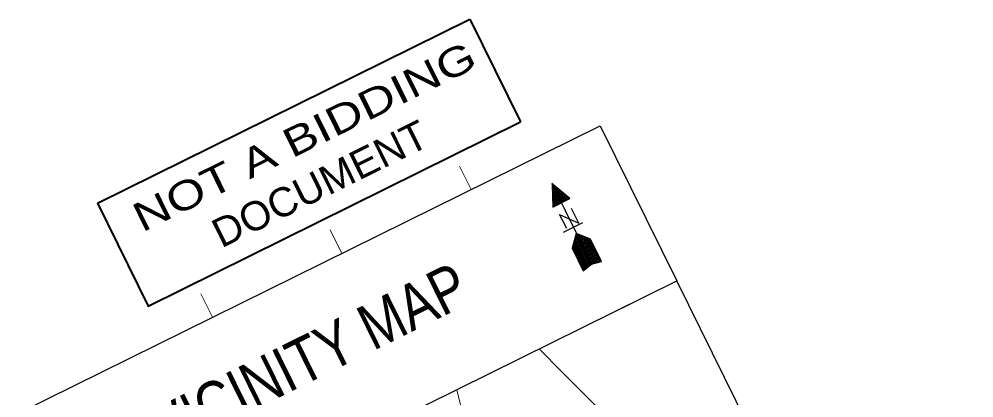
# Model space of a CAD drawing. Extents: x 2356606 to 2371222, y 6973096 to 6982644.
# Drawn here: x 2370560 to 2371222, y 6980646 to 6980908 of the extents above; entities that cross this region are included whole.
import ezdxf
from ezdxf.enums import TextEntityAlignment as Align

# ---------------------------------------------------------------- set-up
doc = ezdxf.new("R2010")
doc.units = 0
doc.header["$LTSCALE"] = 2
doc.layers.add('62', color=7, linetype='Continuous', lineweight=13)
doc.layers.add('63', color=7, linetype='Continuous', lineweight=13)

msp = doc.modelspace()

# ---------------------------------------------------------------- linework, layer by layer
at = {"layer": '62', "lineweight": 40}
for p, q in [((2370614.269, 6980780.584), (2370872.507, 6980908.033)), ((2370872.507, 6980908.033), (2370907.665, 6980836.794))]:
    msp.add_line(p, q, dxfattribs=at)
at = {"layer": '62'}
for p, q in [((2370865.446, 6980806.291), (2370873.467, 6980790.039)), ((2370929.594, 6980793.474), (2370930.018, 6980793.682)), ((2370935.697, 6980780.702), (2370929.603, 6980793.05)), ((2370929.611, 6980792.78), (2370930.539, 6980793.236)), ((2370929.616, 6980792.105), (2370931.07, 6980792.82)), ((2370935.134, 6980780.424), (2370929.635, 6980791.56)), ((2370929.644, 6980791.39), (2370931.602, 6980792.357)), ((2370929.649, 6980790.714), (2370932.111, 6980791.93)), ((2370929.685, 6980790.032), (2370932.633, 6980791.487)), ((2370929.712, 6980789.316), (2370933.162, 6980791.021)), ((2370929.72, 6980788.641), (2370933.673, 6980790.595)), ((2370936.262, 6980780.981), (2370929.968, 6980793.732)), ((2370936.825, 6980781.262), (2370931.171, 6980792.72)), ((2370937.372, 6980781.529), (2370932.353, 6980791.698)), ((2370937.956, 6980781.818), (2370933.564, 6980790.716)), ((2370934.565, 6980780.144), (2370929.685, 6980790.032)), ((2370934, 6980779.865), (2370929.718, 6980788.54)), ((2370929.734, 6980787.948), (2370934.216, 6980790.16)), ((2370929.752, 6980787.252), (2370934.737, 6980789.715)), ((2370933.435, 6980779.586), (2370929.761, 6980787.031)), ((2370929.769, 6980786.558), (2370935.277, 6980789.279)), ((2370929.805, 6980785.875), (2370935.798, 6980788.834)), ((2370932.87, 6980779.307), (2370929.813, 6980785.502)), ((2370929.822, 6980785.181), (2370936.339, 6980788.398)), ((2370929.839, 6980784.487), (2370936.86, 6980787.952)), ((2370932.305, 6980779.029), (2370929.845, 6980784.013)), ((2370929.872, 6980783.096), (2370937.902, 6980787.062)), ((2370929.873, 6980783.802), (2370937.381, 6980787.507)), ((2370929.889, 6980782.402), (2370938.423, 6980786.616)), ((2370929.925, 6980781.717), (2370938.964, 6980786.179)), ((2370929.94, 6980781.024), (2370939.485, 6980785.733)), ((2370929.949, 6980780.351), (2370939.997, 6980785.31)), ((2370929.993, 6980779.646), (2370940.548, 6980784.855)), ((2370930.011, 6980778.95), (2370941.069, 6980784.409)), ((2370930.018, 6980778.275), (2370941.58, 6980783.983)), ((2370938.521, 6980782.097), (2370934.767, 6980789.704)), ((2370939.065, 6980782.364), (2370935.939, 6980788.702)), ((2370939.651, 6980782.654), (2370937.162, 6980787.698)), ((2370940.196, 6980782.924), (2370938.344, 6980786.677)), ((2370940.761, 6980783.202), (2370939.536, 6980785.685)), ((2370941.346, 6980783.491), (2370940.758, 6980784.682)), ((2370931.742, 6980778.751), (2370929.897, 6980782.483)), ((2370931.175, 6980778.471), (2370929.932, 6980780.994)), ((2370930.61, 6980778.192), (2370929.985, 6980779.463)), ((2370930.065, 6980777.923), (2370930.035, 6980777.984)), ((2370775.769, 6980762.032), (2370783.79, 6980745.78)), ((2370944.683, 6980753.947), (2370951.849, 6980757.482)), ((2370944.921, 6980754.74), (2370951.074, 6980757.779)), ((2370945.145, 6980755.556), (2370950.291, 6980758.095)), ((2370945.381, 6980756.397), (2370949.518, 6980758.441)), ((2370945.618, 6980757.192), (2370948.745, 6980758.737)), ((2370955.648, 6980737.426), (2370945.707, 6980757.564)), ((2370945.842, 6980758.007), (2370947.983, 6980759.062)), ((2370956.157, 6980737.826), (2370945.968, 6980758.471)), ((2370946.07, 6980758.82), (2370947.199, 6980759.38)), ((2370956.65, 6980738.246), (2370946.223, 6980759.373)), ((2370957.225, 6980738.505), (2370946.847, 6980759.532)), ((2370957.85, 6980738.663), (2370947.732, 6980759.163)), ((2370958.455, 6980738.809), (2370948.595, 6980758.788)), ((2370959.111, 6980738.959), (2370949.489, 6980758.451)), ((2370959.725, 6980739.137), (2370950.372, 6980758.084)), ((2370960.339, 6980739.263), (2370951.226, 6980757.728)), ((2370943.513, 6980749.152), (2370956.287, 6980755.459)), ((2370943.537, 6980749.867), (2370955.723, 6980755.883)), ((2370943.751, 6980750.653), (2370954.948, 6980756.178)), ((2370943.791, 6980748.589), (2370956.566, 6980754.894)), ((2370952.173, 6980734.506), (2370943.915, 6980751.233)), ((2370943.987, 6980751.496), (2370954.177, 6980756.525)), ((2370944.07, 6980748.024), (2370956.843, 6980754.328)), ((2370952.667, 6980734.924), (2370944.169, 6980752.138)), ((2370944.212, 6980752.309), (2370953.394, 6980756.841)), ((2370944.35, 6980747.456), (2370957.122, 6980753.761)), ((2370953.162, 6980735.345), (2370944.428, 6980753.042)), ((2370944.468, 6980753.114), (2370952.622, 6980757.136)), ((2370944.628, 6980746.892), (2370957.402, 6980753.195)), ((2370953.668, 6980735.744), (2370944.683, 6980753.947)), ((2370944.908, 6980746.325), (2370957.682, 6980752.631)), ((2370954.163, 6980736.164), (2370944.94, 6980754.852)), ((2370945.187, 6980745.761), (2370957.959, 6980752.065)), ((2370954.658, 6980736.585), (2370945.196, 6980755.756)), ((2370955.155, 6980737.005), (2370945.452, 6980756.66)), ((2370945.465, 6980745.197), (2370958.239, 6980751.5)), ((2370945.742, 6980744.631), (2370958.517, 6980750.936)), ((2370960.981, 6980739.431), (2370952.129, 6980757.371)), ((2370961.588, 6980739.579), (2370952.993, 6980756.994)), ((2370962.212, 6980739.739), (2370953.877, 6980756.628)), ((2370962.857, 6980739.904), (2370954.78, 6980756.271)), ((2370963.462, 6980740.053), (2370955.634, 6980755.915)), ((2370951.182, 6980733.666), (2370943.402, 6980749.425)), ((2370951.696, 6980734.094), (2370943.678, 6980750.34)), ((2370946.021, 6980744.065), (2370958.794, 6980750.37)), ((2370946.303, 6980743.503), (2370959.075, 6980749.805)), ((2370946.572, 6980742.958), (2370959.344, 6980749.26)), ((2370946.859, 6980742.372), (2370959.634, 6980748.677)), ((2370947.138, 6980741.807), (2370959.911, 6980748.111)), ((2370947.409, 6980741.262), (2370960.181, 6980747.567)), ((2370947.696, 6980740.677), (2370960.469, 6980746.981)), ((2370947.964, 6980740.133), (2370960.739, 6980746.437)), ((2370948.244, 6980739.566), (2370961.016, 6980745.872)), ((2370948.532, 6980738.982), (2370961.305, 6980745.286)), ((2370948.801, 6980738.438), (2370961.574, 6980744.742)), ((2370949.08, 6980737.871), (2370961.853, 6980744.177)), ((2370949.36, 6980737.309), (2370962.132, 6980743.61)), ((2370949.637, 6980736.743), (2370962.412, 6980743.048)), ((2370949.917, 6980736.176), (2370962.689, 6980742.482)), ((2370950.196, 6980735.611), (2370962.968, 6980741.917)), ((2370950.472, 6980735.047), (2370956.205, 6980737.877)), ((2370957.717, 6980738.623), (2370963.247, 6980741.352)), ((2370960.6, 6980739.344), (2370963.528, 6980740.786)), ((2370963.44, 6980740.043), (2370963.805, 6980740.22)), ((2370950.753, 6980734.481), (2370954.163, 6980736.164)), ((2370951.033, 6980733.919), (2370952.121, 6980734.454)), ((2370686.091, 6980717.773), (2370694.112, 6980701.521)), ((2370919.289, 6980678.805), (2370986.2, 6980711.827))]:
    msp.add_line(p, q, dxfattribs=at)
at = {"layer": '62', "lineweight": 25}
for p, q in [((2370929.439, 6980794.248), (2370957.102, 6980738.193)), ((2370937.524, 6980760.524), (2370950.924, 6980767.137)), ((2370613.001, 6980527.892), (2371016.165, 6980726.869))]:
    msp.add_line(p, q, dxfattribs=at)
for points in [[(2370613.001, 6980527.892), (2370559.983, 6980635.323), (2370962.843, 6980834.15), (2371016.165, 6980726.869)], [(2370929.564, 6980793.987), (2370930.025, 6980777.904), (2370941.869, 6980783.749), (2370929.507, 6980794.108)], [(2370939.7, 6980762.978), (2370934.831, 6980772.844), (2370948.071, 6980766.659), (2370943.023, 6980776.889)], [(2370946.305, 6980759.614), (2370943.393, 6980749.394), (2370951.161, 6980733.656), (2370956.842, 6980738.417), (2370963.846, 6980740.142), (2370956.166, 6980755.698), (2370946.506, 6980759.664)], [(2370613.001, 6980527.892), (2370818.917, 6980110.665), (2371222.081, 6980309.64), (2371016.165, 6980726.869)], [(2370920.544, 6980679.674), (2370936.659, 6980663.489), (2370962.929, 6980637.158), (2370992.577, 6980626.045), (2371024.155, 6980615.857), (2371028.102, 6980612.689)]]:
    msp.add_lwpolyline(points, dxfattribs=at)
at = {"layer": '62', "lineweight": 40}
msp.add_lwpolyline([(2370614.269, 6980780.584), (2370649.427, 6980709.346), (2370907.665, 6980836.794)], dxfattribs=at)
at = {"layer": '62'}
msp.add_lwpolyline([(2370879.15, 6980528.283), (2370879.008, 6980590.094), (2370863.546, 6980651.068)], dxfattribs=at)
at = {"layer": '63', "lineweight": 40}
for p, q in [((2370614.269, 6980780.584), (2370872.507, 6980908.033)), ((2370872.507, 6980908.033), (2370907.665, 6980836.794))]:
    msp.add_line(p, q, dxfattribs=at)
at = {"layer": '63'}
for p, q in [((2370865.446, 6980806.291), (2370873.467, 6980790.039)), ((2370929.594, 6980793.474), (2370930.018, 6980793.682)), ((2370935.697, 6980780.702), (2370929.603, 6980793.05)), ((2370929.611, 6980792.78), (2370930.539, 6980793.236)), ((2370929.616, 6980792.105), (2370931.07, 6980792.82)), ((2370935.134, 6980780.424), (2370929.635, 6980791.56)), ((2370929.644, 6980791.39), (2370931.602, 6980792.357)), ((2370929.649, 6980790.714), (2370932.111, 6980791.93)), ((2370929.685, 6980790.032), (2370932.633, 6980791.487)), ((2370929.712, 6980789.316), (2370933.162, 6980791.021)), ((2370929.72, 6980788.641), (2370933.673, 6980790.595)), ((2370936.262, 6980780.981), (2370929.968, 6980793.732)), ((2370936.825, 6980781.262), (2370931.171, 6980792.72)), ((2370937.372, 6980781.529), (2370932.353, 6980791.698)), ((2370937.956, 6980781.818), (2370933.564, 6980790.716)), ((2370934.565, 6980780.144), (2370929.685, 6980790.032)), ((2370934, 6980779.865), (2370929.718, 6980788.54)), ((2370929.734, 6980787.948), (2370934.216, 6980790.16)), ((2370929.752, 6980787.252), (2370934.737, 6980789.715)), ((2370933.435, 6980779.586), (2370929.761, 6980787.031)), ((2370929.769, 6980786.558), (2370935.277, 6980789.279)), ((2370929.805, 6980785.875), (2370935.798, 6980788.834)), ((2370932.87, 6980779.307), (2370929.813, 6980785.502)), ((2370929.822, 6980785.181), (2370936.339, 6980788.398)), ((2370929.839, 6980784.487), (2370936.86, 6980787.952)), ((2370932.305, 6980779.029), (2370929.845, 6980784.013)), ((2370929.872, 6980783.096), (2370937.902, 6980787.062)), ((2370929.873, 6980783.802), (2370937.381, 6980787.507)), ((2370929.889, 6980782.402), (2370938.423, 6980786.616)), ((2370929.925, 6980781.717), (2370938.964, 6980786.179)), ((2370929.94, 6980781.024), (2370939.485, 6980785.733)), ((2370929.949, 6980780.351), (2370939.997, 6980785.31)), ((2370929.993, 6980779.646), (2370940.548, 6980784.855)), ((2370930.011, 6980778.95), (2370941.069, 6980784.409)), ((2370930.018, 6980778.275), (2370941.58, 6980783.983)), ((2370938.521, 6980782.097), (2370934.767, 6980789.704)), ((2370939.065, 6980782.364), (2370935.939, 6980788.702)), ((2370939.651, 6980782.654), (2370937.162, 6980787.698)), ((2370940.196, 6980782.924), (2370938.344, 6980786.677)), ((2370940.761, 6980783.202), (2370939.536, 6980785.685)), ((2370941.346, 6980783.491), (2370940.758, 6980784.682)), ((2370931.742, 6980778.751), (2370929.897, 6980782.483)), ((2370931.175, 6980778.471), (2370929.932, 6980780.994)), ((2370930.61, 6980778.192), (2370929.985, 6980779.463)), ((2370930.065, 6980777.923), (2370930.035, 6980777.984)), ((2370775.769, 6980762.032), (2370783.79, 6980745.78)), ((2370944.683, 6980753.947), (2370951.849, 6980757.482)), ((2370944.921, 6980754.74), (2370951.074, 6980757.779)), ((2370945.145, 6980755.556), (2370950.291, 6980758.095)), ((2370945.381, 6980756.397), (2370949.518, 6980758.441)), ((2370945.618, 6980757.192), (2370948.745, 6980758.737)), ((2370955.648, 6980737.426), (2370945.707, 6980757.564)), ((2370945.842, 6980758.007), (2370947.983, 6980759.062)), ((2370956.157, 6980737.826), (2370945.968, 6980758.471)), ((2370946.07, 6980758.82), (2370947.199, 6980759.38)), ((2370956.65, 6980738.246), (2370946.223, 6980759.373)), ((2370957.225, 6980738.505), (2370946.847, 6980759.532)), ((2370957.85, 6980738.663), (2370947.732, 6980759.163)), ((2370958.455, 6980738.809), (2370948.595, 6980758.788)), ((2370959.111, 6980738.959), (2370949.489, 6980758.451)), ((2370959.725, 6980739.137), (2370950.372, 6980758.084)), ((2370960.339, 6980739.263), (2370951.226, 6980757.728)), ((2370943.513, 6980749.152), (2370956.287, 6980755.459)), ((2370943.537, 6980749.867), (2370955.723, 6980755.883)), ((2370943.751, 6980750.653), (2370954.948, 6980756.178)), ((2370943.791, 6980748.589), (2370956.566, 6980754.894)), ((2370952.173, 6980734.506), (2370943.915, 6980751.233)), ((2370943.987, 6980751.496), (2370954.177, 6980756.525)), ((2370944.07, 6980748.024), (2370956.843, 6980754.328)), ((2370952.667, 6980734.924), (2370944.169, 6980752.138)), ((2370944.212, 6980752.309), (2370953.394, 6980756.841)), ((2370944.35, 6980747.456), (2370957.122, 6980753.761)), ((2370953.162, 6980735.345), (2370944.428, 6980753.042)), ((2370944.468, 6980753.114), (2370952.622, 6980757.136)), ((2370944.628, 6980746.892), (2370957.402, 6980753.195)), ((2370953.668, 6980735.744), (2370944.683, 6980753.947)), ((2370944.908, 6980746.325), (2370957.682, 6980752.631)), ((2370954.163, 6980736.164), (2370944.94, 6980754.852)), ((2370945.187, 6980745.761), (2370957.959, 6980752.065)), ((2370954.658, 6980736.585), (2370945.196, 6980755.756)), ((2370955.155, 6980737.005), (2370945.452, 6980756.66)), ((2370945.465, 6980745.197), (2370958.239, 6980751.5)), ((2370945.742, 6980744.631), (2370958.517, 6980750.936)), ((2370960.981, 6980739.431), (2370952.129, 6980757.371)), ((2370961.588, 6980739.579), (2370952.993, 6980756.994)), ((2370962.212, 6980739.739), (2370953.877, 6980756.628)), ((2370962.857, 6980739.904), (2370954.78, 6980756.271)), ((2370963.462, 6980740.053), (2370955.634, 6980755.915)), ((2370951.182, 6980733.666), (2370943.402, 6980749.425)), ((2370951.696, 6980734.094), (2370943.678, 6980750.34)), ((2370946.021, 6980744.065), (2370958.794, 6980750.37)), ((2370946.303, 6980743.503), (2370959.075, 6980749.805)), ((2370946.572, 6980742.958), (2370959.344, 6980749.26)), ((2370946.859, 6980742.372), (2370959.634, 6980748.677)), ((2370947.138, 6980741.807), (2370959.911, 6980748.111)), ((2370947.409, 6980741.262), (2370960.181, 6980747.567)), ((2370947.696, 6980740.677), (2370960.469, 6980746.981)), ((2370947.964, 6980740.133), (2370960.739, 6980746.437)), ((2370948.244, 6980739.566), (2370961.016, 6980745.872)), ((2370948.532, 6980738.982), (2370961.305, 6980745.286)), ((2370948.801, 6980738.438), (2370961.574, 6980744.742)), ((2370949.08, 6980737.871), (2370961.853, 6980744.177)), ((2370949.36, 6980737.309), (2370962.132, 6980743.61)), ((2370949.637, 6980736.743), (2370962.412, 6980743.048)), ((2370949.917, 6980736.176), (2370962.689, 6980742.482)), ((2370950.196, 6980735.611), (2370962.968, 6980741.917)), ((2370950.472, 6980735.047), (2370956.205, 6980737.877)), ((2370957.717, 6980738.623), (2370963.247, 6980741.352)), ((2370960.6, 6980739.344), (2370963.528, 6980740.786)), ((2370963.44, 6980740.043), (2370963.805, 6980740.22)), ((2370950.753, 6980734.481), (2370954.163, 6980736.164)), ((2370951.033, 6980733.919), (2370952.121, 6980734.454)), ((2370686.091, 6980717.773), (2370694.112, 6980701.521)), ((2370919.289, 6980678.805), (2370986.2, 6980711.827))]:
    msp.add_line(p, q, dxfattribs=at)
at = {"layer": '63', "lineweight": 25}
for p, q in [((2370929.439, 6980794.248), (2370957.102, 6980738.193)), ((2370937.524, 6980760.524), (2370950.924, 6980767.137)), ((2370613.001, 6980527.892), (2371016.165, 6980726.869))]:
    msp.add_line(p, q, dxfattribs=at)
for points in [[(2370613.001, 6980527.892), (2370559.983, 6980635.323), (2370962.843, 6980834.15), (2371016.165, 6980726.869)], [(2370929.564, 6980793.987), (2370930.025, 6980777.904), (2370941.869, 6980783.749), (2370929.507, 6980794.108)], [(2370939.7, 6980762.978), (2370934.831, 6980772.844), (2370948.071, 6980766.659), (2370943.023, 6980776.889)], [(2370946.305, 6980759.614), (2370943.393, 6980749.394), (2370951.161, 6980733.656), (2370956.842, 6980738.417), (2370963.846, 6980740.142), (2370956.166, 6980755.698), (2370946.506, 6980759.664)], [(2370613.001, 6980527.892), (2370818.917, 6980110.665), (2371222.081, 6980309.64), (2371016.165, 6980726.869)], [(2370920.544, 6980679.674), (2370936.659, 6980663.489), (2370962.929, 6980637.158), (2370992.577, 6980626.045), (2371024.155, 6980615.857), (2371028.102, 6980612.689)]]:
    msp.add_lwpolyline(points, dxfattribs=at)
at = {"layer": '63', "lineweight": 40}
msp.add_lwpolyline([(2370614.269, 6980780.584), (2370649.427, 6980709.346), (2370907.665, 6980836.794)], dxfattribs=at)
at = {"layer": '63'}
msp.add_lwpolyline([(2370879.15, 6980528.283), (2370879.008, 6980590.094), (2370863.546, 6980651.068)], dxfattribs=at)

# ---------------------------------------------------------------- texts
at = {"layer": '62'}
for s, width, p in [('NOT A BIDDING', 1.3, (2370762.27, 6980817.868)), ('DOCUMENT', 1.05, (2370773.049, 6980785.045))]:
    msp.add_text(s, height=20, rotation=26.268, dxfattribs=dict(at, width=width)).set_placement(p, align=Align.CENTER)
at = {"layer": '62', "width": 0.85}
msp.add_text('VICINITY MAP', height=31.45, rotation=26.268, dxfattribs=at).set_placement((2370661.092, 6980606.884))
at = {"layer": '63'}
for s, width, p in [('NOT A BIDDING', 1.3, (2370762.27, 6980817.868)), ('DOCUMENT', 1.05, (2370773.049, 6980785.045))]:
    msp.add_text(s, height=20, rotation=26.268, dxfattribs=dict(at, width=width)).set_placement(p, align=Align.CENTER)
at = {"layer": '63', "width": 0.85}
msp.add_text('VICINITY MAP', height=31.45, rotation=26.268, dxfattribs=at).set_placement((2370661.092, 6980606.884))

doc.saveas('drawing.dxf')
